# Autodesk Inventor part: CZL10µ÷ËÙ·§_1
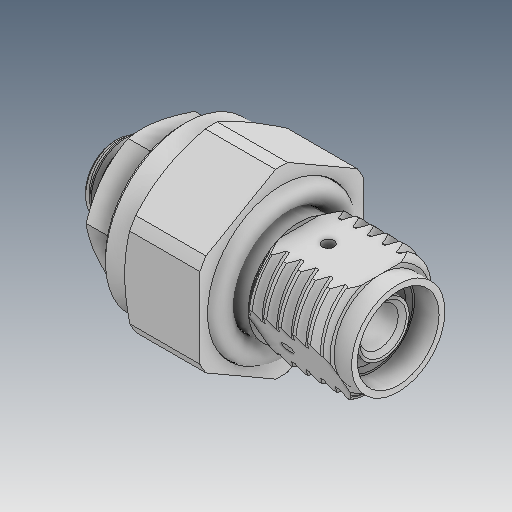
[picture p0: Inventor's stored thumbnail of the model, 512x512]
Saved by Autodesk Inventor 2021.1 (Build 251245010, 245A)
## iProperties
Created: 2019-05
Part Number: CZL10µ÷ËÙ·§_1
Material: Ogólny
Document SubType Name: Modeling
Designer: user
Density: 1 g/cm^3
Appearance: Domyślna
Author: user
Revision Number: ÈÎºÎ
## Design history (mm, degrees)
feature "ÊäÈë2"
feature "ÊäÈë3"
feature "ÊäÈë5"
node "Bryła1"
node "Bryła2"
node "Bryła3"
